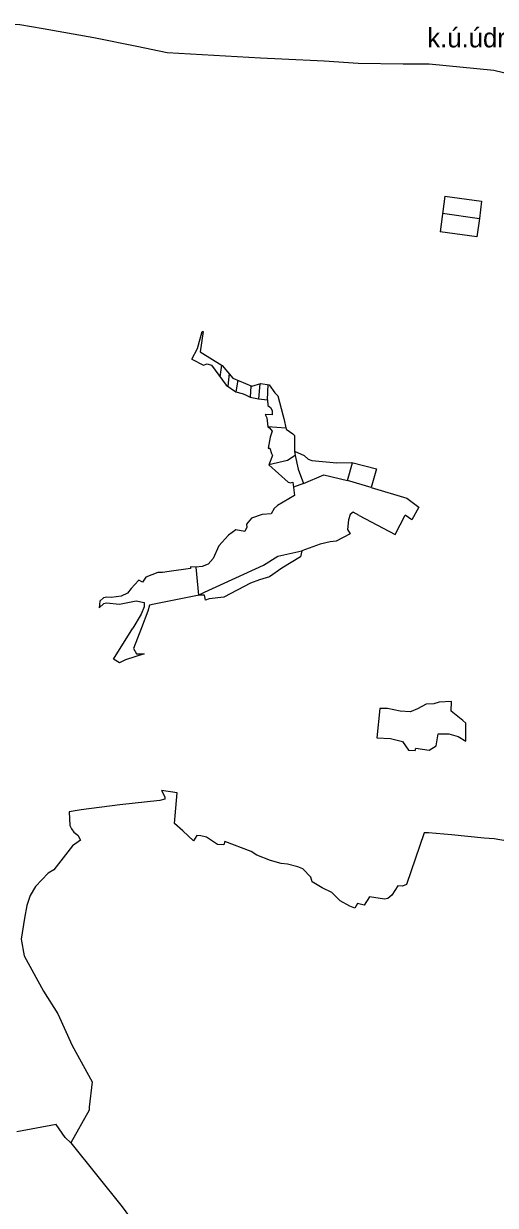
# Model space of a CAD drawing. Extents: x -764981 to -759318, y -1137368 to -1131930.
# Drawn here: x -763217 to -762113, y -1134785 to -1132018 of the extents above; entities that cross this region are included whole.
import ezdxf

# ---------------------------------------------------------------- set-up
doc = ezdxf.new("R2010")
doc.units = 0
for name, color, linetype in [('Vrstva 41', 7, 'Continuous'), ('Vrstva 42', 7, 'Continuous'), ('Vrstva 43', 7, 'Continuous'), ('Vrstva 44', 7, 'Continuous'), ('Vrstva 45', 7, 'Continuous')]:
    doc.layers.add(name, color=color, linetype=linetype)

msp = doc.modelspace()

# ---------------------------------------------------------------- linework, layer by layer
at = {"layer": 'Vrstva 41'}
for p, q in [((-762434.2, -1132110.6), (-762328.6, -1132111.8)), ((-762279.3, -1133912.3), (-762321, -1134033.1)), ((-763063.9, -1134561.9), (-763106.6, -1134638.3))]:
    msp.add_line(p, q, dxfattribs=at)
for points in [[(-763316.6, -1132017.9), (-763267.7, -1132017.9), (-763226.4, -1132020), (-763171.7, -1132029)], [(-763171.7, -1132029), (-763053.1, -1132050.1), (-762952.6, -1132070.8)], [(-762952.6, -1132070.8), (-762881.5, -1132085.6), (-762663.1, -1132097.7), (-762613, -1132100.5)], [(-762613, -1132100.5), (-762513.6, -1132104.7), (-762434.2, -1132110.6)], [(-762328.6, -1132111.8), (-762267.8, -1132111.8), (-762116.8, -1132126.6), (-761980.9, -1132159.3)], [(-762864.3, -1133890.4), (-762857.6, -1133818.7), (-762894.7, -1133813.7), (-762886.9, -1133828), (-762886.9, -1133833.4)], [(-762992, -1133847.1), (-763082.7, -1133858.4), (-763110.7, -1133863.5), (-763109.1, -1133895.2)], [(-762886.9, -1133833.4), (-762898.3, -1133836.4), (-762992, -1133847.1)], [(-763109.1, -1133895.2), (-763105.5, -1133903.2), (-763099.9, -1133911), (-763090.6, -1133918.3), (-763084.4, -1133929.8)], [(-762614, -1133984.3), (-762639, -1133977.1), (-762671.5, -1133964.9), (-762684.6, -1133956.5), (-762746.3, -1133932.6), (-762748.9, -1133940.7), (-762763.4, -1133939.9), (-762789.3, -1133922.8), (-762802.2, -1133919.4), (-762812, -1133918.5), (-762819.9, -1133930.9), (-762844.3, -1133907.4), (-762864.3, -1133890.4)], [(-763084.4, -1133929.8), (-763102.8, -1133943.2), (-763146.5, -1133999.4)], [(-762019.4, -1133954.7), (-762046.2, -1133943.4), (-762084.5, -1133932), (-762115.9, -1133926.8), (-762138.9, -1133924.6), (-762215.9, -1133917.4), (-762269.7, -1133912.3), (-762279.3, -1133912.3)], [(-762476.3, -1134071.3), (-762495.5, -1134052.1), (-762518, -1134041.6), (-762541.4, -1134027.5), (-762545, -1134016), (-762563.8, -1133996.8), (-762575.7, -1133992.2), (-762599.3, -1133986), (-762614, -1133984.3)], [(-763146.5, -1133999.4), (-763159.5, -1134006.5), (-763189.4, -1134038.3), (-763201.9, -1134059), (-763209.6, -1134082.7), (-763215.1, -1134112.3)], [(-762321, -1134033.1), (-762330.5, -1134037.2), (-762341.1, -1134036.2), (-762355.4, -1134058.1), (-762364.4, -1134066), (-762372.5, -1134067.7), (-762407.7, -1134062.2), (-762419.7, -1134082), (-762435.5, -1134078.2), (-762442.1, -1134089.1), (-762453.4, -1134084.5), (-762476.3, -1134071.3)], [(-763215.1, -1134112.3), (-763222.8, -1134161.4), (-763215.8, -1134200.2)], [(-763215.8, -1134200.2), (-763170.6, -1134283.3), (-763137.4, -1134336.1), (-763103.8, -1134410.4)], [(-763103.8, -1134410.4), (-763056.9, -1134495.7), (-763063.9, -1134554.6), (-763063.9, -1134561.9)], [(-763106.6, -1134638.3), (-763119.7, -1134626.1), (-763141.3, -1134595), (-763233.3, -1134612.5)]]:
    msp.add_lwpolyline(points, dxfattribs=at)
at = {"layer": 'Vrstva 42'}
for p, q in [((-762231.3, -1132421.9), (-762242.5, -1132505.5)), ((-762456.6, -1133179.3), (-762459, -1133202.1)), ((-762453.1, -1133167.3), (-762456.6, -1133179.3)), ((-762445.8, -1133162), (-762453.1, -1133167.3)), ((-762431.7, -1133169.7), (-762445.8, -1133162)), ((-762431.7, -1133169.7), (-762347.4, -1133214)), ((-762347.4, -1133214), (-762324.2, -1133168.8)), ((-762452.6, -1133212.1), (-762485.9, -1133229.4)), ((-762459, -1133202.1), (-762452.6, -1133212.1)), ((-762523.1, -1133236.3), (-762566.2, -1133252.1)), ((-762499.9, -1133230.9), (-762523.1, -1133236.3)), ((-762485.9, -1133229.4), (-762499.9, -1133230.9)), ((-762310.3, -1133628.5), (-762311.7, -1133628.8))]:
    msp.add_line(p, q, dxfattribs=at)
for points in [[(-762231.3, -1132421.9), (-762145, -1132433.4), (-762150.4, -1132473.8), (-762156.1, -1132516.9), (-762242.5, -1132505.5)], [(-762823.7, -1132803.1), (-762810.1, -1132778.6), (-762799.1, -1132738.4), (-762796.8, -1132739), (-762804.1, -1132786.5), (-762752.6, -1132818.3), (-762727.2, -1132847.6), (-762683.4, -1132867), (-762662, -1132860.6), (-762642.6, -1132863.2), (-762628.9, -1132881.9)], [(-762823.7, -1132803.1), (-762796, -1132817.2), (-762787.8, -1132814.2), (-762777.6, -1132817.7), (-762743.2, -1132864), (-762720.3, -1132880), (-762706, -1132884.1)], [(-762706, -1132884.1), (-762699.3, -1132885.8), (-762687.1, -1132892.7), (-762667.5, -1132896.1), (-762646.6, -1132898.6), (-762645.8, -1132912.1)], [(-762628.9, -1132881.9), (-762622.2, -1132889.4), (-762610.7, -1132934)], [(-762645.8, -1132912.1), (-762639.4, -1132916.9), (-762635.7, -1132923.9), (-762635.5, -1132933.8), (-762651.6, -1132933.4)], [(-762651.6, -1132933.4), (-762648.2, -1132940.7), (-762645.5, -1132962), (-762641.6, -1132964.4), (-762635.1, -1132971.8), (-762640.1, -1132985.7), (-762645.1, -1133012), (-762641, -1133011.7), (-762636.8, -1133024.2)], [(-762610.7, -1132934), (-762608.4, -1132942.2), (-762602.8, -1132967.1), (-762586.9, -1132977.9)], [(-762586.9, -1132977.9), (-762582.9, -1132982), (-762582.9, -1133018.8)], [(-762582.9, -1133018.8), (-762560.5, -1133028.7), (-762550.9, -1133037.7), (-762542.4, -1133040.4), (-762483.8, -1133045.8), (-762448.6, -1133045.6), (-762391.3, -1133059.9)], [(-762636.8, -1133024.2), (-762634.9, -1133028.9), (-762643, -1133050.5), (-762598.3, -1133091.8), (-762592.9, -1133092.8), (-762586.7, -1133091.3), (-762582.8, -1133122.5), (-762623.1, -1133146.2), (-762630.6, -1133153.2)], [(-762391.3, -1133059.9), (-762403.4, -1133103.7), (-762320.2, -1133128.8), (-762292.1, -1133150.3), (-762308.2, -1133179.5), (-762324.2, -1133168.8)], [(-762630.6, -1133153.2), (-762637.5, -1133165.5), (-762659.1, -1133167.4), (-762684.2, -1133175.7), (-762695.5, -1133189.9), (-762694.9, -1133196.9), (-762699.5, -1133207.2), (-762720.6, -1133202.8), (-762737.7, -1133215.2), (-762760.6, -1133240.8), (-762773.7, -1133269.8), (-762785.4, -1133283.1), (-762799, -1133288.6), (-762814, -1133290.5), (-762826.5, -1133289.7), (-762826.8, -1133293.8), (-762876.7, -1133300.6)], [(-762566.2, -1133252.1), (-762569.1, -1133266.4), (-762612.9, -1133292.9), (-762641.4, -1133312.9), (-762665.4, -1133319.8), (-762686.4, -1133328.3), (-762748.8, -1133360.5)], [(-762947.7, -1133320.6), (-762948.2, -1133321.8), (-762965.9, -1133340.5), (-762974.2, -1133351.3), (-762989, -1133358.7), (-763012.6, -1133361.8), (-763022.9, -1133360.9), (-763030.5, -1133362.3)], [(-762930.9, -1133313.8), (-762939.2, -1133325.4), (-762947.7, -1133320.6)], [(-762876.7, -1133300.6), (-762892.3, -1133303.1), (-762902.8, -1133303), (-762930.9, -1133313.8)], [(-763030.5, -1133362.3), (-763039.2, -1133370.2), (-763040.5, -1133385.5), (-763029.4, -1133375.6)], [(-763029.4, -1133375.6), (-763023.3, -1133374.3), (-762993.1, -1133377.3), (-762954.2, -1133369.5), (-762935.4, -1133373.1), (-762934.9, -1133383.4), (-762942.1, -1133400.7), (-762961.7, -1133433)], [(-762911.4, -1133377.4), (-762923, -1133379.4), (-762926.7, -1133393.1), (-762941.1, -1133432.2)], [(-762748.8, -1133360.5), (-762783, -1133364.8), (-762791.4, -1133368), (-762793.7, -1133355.8), (-762806.2, -1133355.8), (-762911.4, -1133377.4)], [(-762941.1, -1133432.2), (-762960.4, -1133481.2), (-762953.3, -1133493.4), (-762935.1, -1133493.4), (-762978.5, -1133507.3), (-762993, -1133514.5), (-763007, -1133505.9), (-762961.7, -1133433)], [(-762311.7, -1133628.8), (-762335.5, -1133627.5), (-762365.7, -1133621.2), (-762383.1, -1133621.1), (-762390.5, -1133689.7), (-762358.4, -1133691.7), (-762330.3, -1133698.4), (-762316.5, -1133719), (-762300.8, -1133719.3), (-762298.8, -1133714.6), (-762267.9, -1133719.2), (-762251.2, -1133708.8), (-762246.5, -1133680.9)], [(-762246.5, -1133680.9), (-762221.9, -1133680.9), (-762200.1, -1133687.1), (-762182.4, -1133698.1), (-762182.3, -1133655.8), (-762188.8, -1133649.2), (-762216.6, -1133627.3), (-762215.7, -1133605), (-762244.6, -1133606.3), (-762256.7, -1133610.1), (-762275, -1133611.2), (-762295, -1133622.2), (-762310.3, -1133628.5)]]:
    msp.add_lwpolyline(points, dxfattribs=at)
at = {"layer": 'Vrstva 43'}
for p, q in [((-762236.6, -1132461.9), (-762150.4, -1132473.8)), ((-762754.1, -1132817.3), (-762757.6, -1132844.9)), ((-762736.3, -1132837.3), (-762739.3, -1132866.7)), ((-762715.9, -1132852.8), (-762720.3, -1132880)), ((-762685.2, -1132866.5), (-762687.1, -1132892.7)), ((-762664.3, -1132861.4), (-762667.5, -1132896.1)), ((-762646.6, -1132898.6), (-762644.7, -1132863)), ((-762603.3, -1132964.8), (-762645.5, -1132962)), ((-762403.4, -1133103.7), (-762459.3, -1133087.8))]:
    msp.add_line(p, q, dxfattribs=at)
for points in [[(-762582.9, -1133018.8), (-762581.4, -1133029.3), (-762599.9, -1133040.5), (-762643, -1133050.5)], [(-762581.4, -1133029.3), (-762574.2, -1133060.7), (-762561.9, -1133094.3), (-762585.2, -1133102.8)], [(-762561.9, -1133094.3), (-762514.3, -1133074.1), (-762459.3, -1133087.8), (-762447, -1133046)], [(-762793.9, -1133349.3), (-762655.6, -1133285.7), (-762622.2, -1133264.5), (-762566.2, -1133252.1)], [(-762814, -1133290.5), (-762808.1, -1133355.8), (-762793.9, -1133349.3)]]:
    msp.add_lwpolyline(points, dxfattribs=at)
at = {"layer": 'Vrstva 44'}
msp.add_lwpolyline([(-763106.6, -1134638.3), (-762986.3, -1134788.3), (-762901.4, -1134904.5), (-762876.5, -1134931), (-762819.4, -1134963.3)], dxfattribs=at)

# ---------------------------------------------------------------- texts
at = {"layer": 'Vrstva 45'}
msp.add_text('k.ú.údraž', height=45, dxfattribs=at).set_placement((-762272.3, -1132073.5))

doc.saveas('drawing.dxf')
